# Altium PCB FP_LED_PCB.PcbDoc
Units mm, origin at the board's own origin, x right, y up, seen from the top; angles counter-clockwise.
Board outline 54 x 13.5 mm, 2 copper layers (Top Layer, Bottom Layer), stack 1.671 mm thick; 7 components, 7 nets, 16 pads, 2 vias.
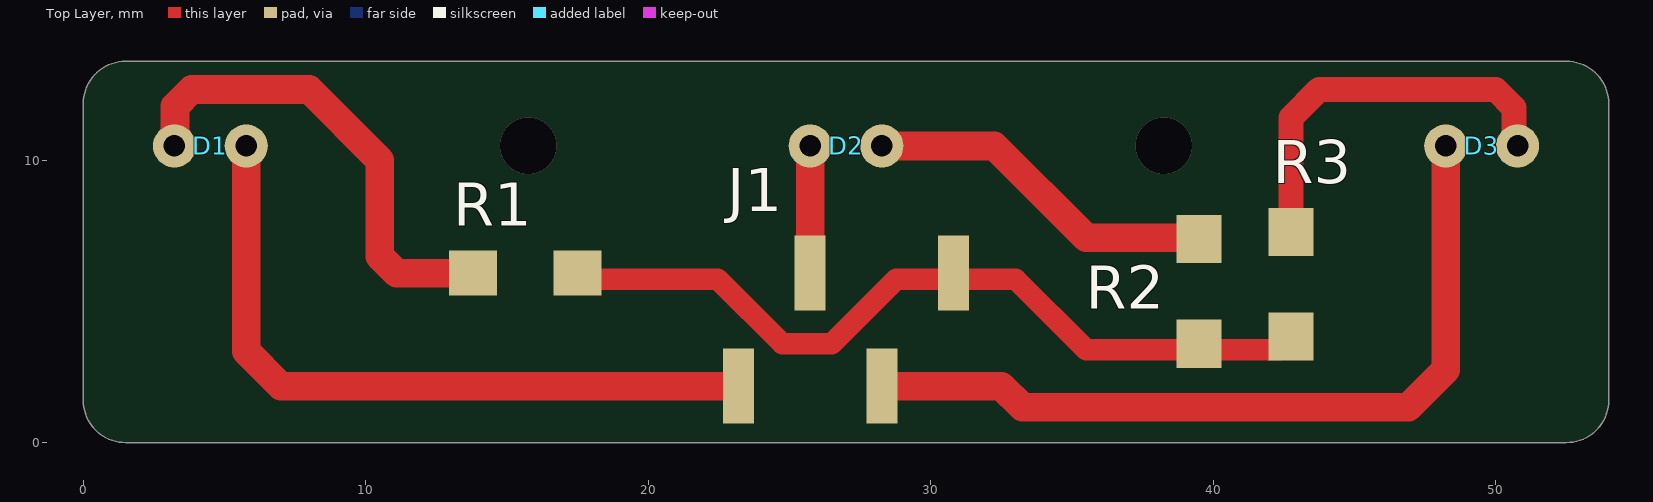
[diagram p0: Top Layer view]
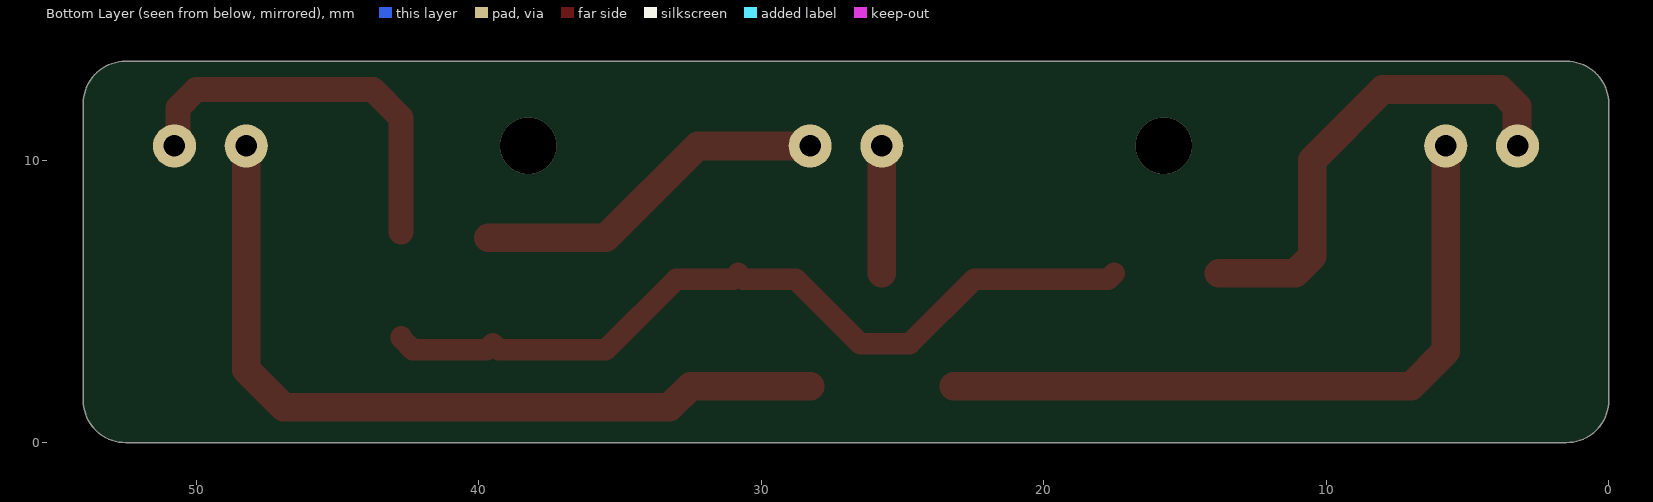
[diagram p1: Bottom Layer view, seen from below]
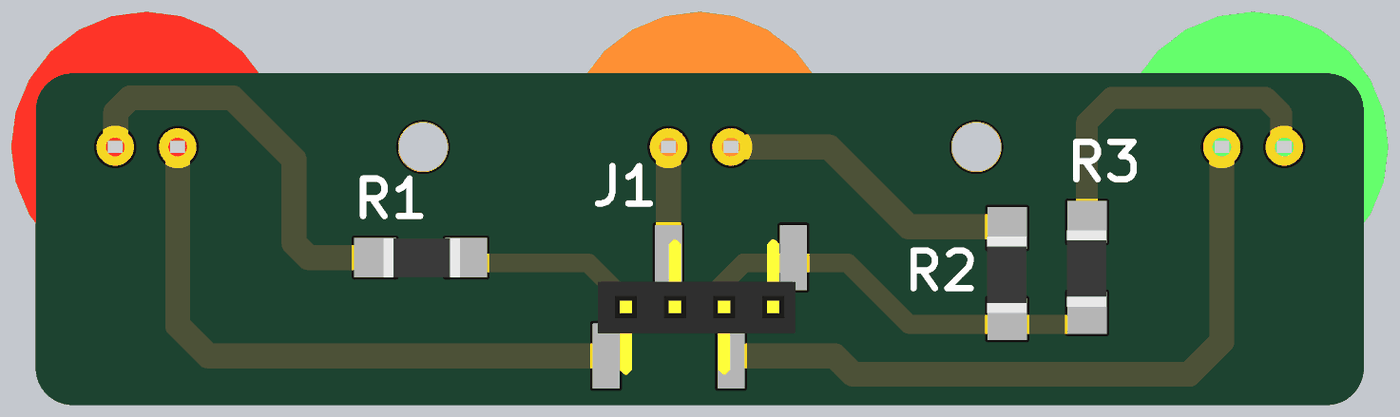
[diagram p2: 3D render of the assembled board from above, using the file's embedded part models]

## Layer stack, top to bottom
Top Solder: solder mask 0.0102, Solder Resist, Dk 3.5
Top Layer: signal copper 0.0356
Dielectric 1: dielectric 1.6, FR-4, Dk 4.8
Bottom Layer: signal copper 0.0356
Bottom Solder: solder mask 0.0102, Solder Resist, Dk 3.5

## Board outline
1.5,0 cw(c1.5,1.5) 0,1.5 0,12 cw(c1.5,12) 1.5,13.5 52.5,13.5 cw(c52.5,12) 54,12 54,1.5 cw(c52.5,1.5) 52.5,0

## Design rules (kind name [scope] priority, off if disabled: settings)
Clearance [All] p1: gap=0.254 ignorepadtopadclearanceinfootprint=FALSE
PolygonConnect [All] p1: connectstyle=Relief reliefconductorwidth=0.254 reliefentries=4 polygonreliefangle="90 Angle" airgapwidth=0.254
RoutingVias [All] p1: holewidth=0.711 width=1.27 viastyle="Through Hole" minholewidth=0.711 minwidth=1.27 maxholewidth=0.711 maxwidth=1.27
SolderMaskExpansion [All] p1: expansion=0.102 istentingtop=FALSE
SupplyNets "Schematic Supply Nets" [InNet('GND')] p1: voltage=0.000
Width [All] p1: maxlimit=1.27 minlimit=0.254 preferedwidth=1.016
30 further rules are at their usual default settings.

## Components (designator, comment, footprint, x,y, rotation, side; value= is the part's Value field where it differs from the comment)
D1 "Led_red" LED_RED_10MM 4.5,10.5 r0 top locked
D2 "Led_orange" LED_ORANGE_10MM 27,10.5 r180 top
D3 "Led_green" LED_GREEN_10MM 49.5,10.5 r180 top
J1 "Header 1x4" HDR4X1_FEMALE 27,4 r90 top
R1 "R499" RES1206 17.5,6 r180 top
R2 "R499" RES1206 39.5,3.5 r90 top
R3 "R499" RES1206 42.75,3.75 r90 top

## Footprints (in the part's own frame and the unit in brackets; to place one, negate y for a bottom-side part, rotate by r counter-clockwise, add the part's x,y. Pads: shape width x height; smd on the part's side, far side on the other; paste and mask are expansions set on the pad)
HDR4X1_FEMALE [mm]
  rect 2.65x1.1 smd: 1(-2,3.81) 2(2,1.27) 3(-2,-1.27) 4(2,-3.81)
  body extent -2.76,-3.89 2.74,4.15, height 2.33
LED_GREEN_10MM [mil]
  round 60 hole 30: 1(-50,0) 2(50,0)
  body extent -217,-216 216,216, height 552
LED_ORANGE_10MM [mil]
  round 60 hole 30: 1(-50,0) 2(50,0)
  body extent -217,-216 216,216, height 552
LED_RED_10MM [mil]
  round 60 hole 30: 1(-50,0) 2(50,0)
  body extent -217,-216 216,216, height 552
RES1206 [mm]
  rect 1.7x1.6 smd: 1(0,0) 2(3.7,0)
  body extent 0.25,-0.79 3.35,0.81, height 0.55

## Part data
D1 D2 D3: "1206"

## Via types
v1: diameter 2, hole 2, Top Layer to Bottom Layer, 2 vias

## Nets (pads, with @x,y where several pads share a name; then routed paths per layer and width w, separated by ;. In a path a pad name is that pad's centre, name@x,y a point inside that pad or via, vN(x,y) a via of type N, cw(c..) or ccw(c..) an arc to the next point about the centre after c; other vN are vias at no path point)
GND: J1.4 R1.1 R2.1 R3.1 | length 28.9
  Top Layer w0.762: R1.1 17.716,5.784 22.466,5.784 24.75,3.5 26.5,3.5 28.784,5.784 30.641,5.784 J1.4@30.81,5.953 ; J1.4 J1.4@30.81,5.953 ; R3.1 42.75,3.703 42.331,3.284 39.716,3.284 R2.1 39.284,3.284 35.5,3.284 33,5.784 30.979,5.784 J1.4@30.81,5.953
NetD1_1: D1.1 R1.2 | length 16.9
  Top Layer w1.016: D1.1 3.25,10.52 3.25,11.905 3.845,12.5 8,12.5 10.5,10 10.5,6.595 11.095,6 R1.2
NetD1_2: D1.2 J1.1 | length 25.2
  Top Layer w1.016: D1.2 5.77,3.23 7,2 J1.1
NetD2_1: D2.1 R2.2 | length 12.7
  Top Layer w1.016: D2.1 32.25,10.5 35.5,7.25 R2.2@39.653,7.25
NetD2_2: D2.2 J1.2 | length 4.5
  Top Layer w1.016: J1.2 D2.2
NetD3_1: D3.1 R3.2 | length 14
  Top Layer w0.889: R3.2 42.75,11.5 43.75,12.5 50,12.5 50.648,11.852 50.648,10.622 D3.1
NetD3_2: D3.2 J1.3 | length 28.7
  Top Layer w1.016: J1.3 32.5,2 33.25,1.25 46.905,1.25 48.23,2.575 D3.2
copper on no net:
  other v1: 15.75,10.5 38.25,10.5

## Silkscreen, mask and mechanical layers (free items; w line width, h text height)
Mechanical 1:
  the board outline again, w0.254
